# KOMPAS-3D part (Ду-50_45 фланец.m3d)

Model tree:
1. Операция без истории:1
2. Операция без истории:2
3. Операция без истории:3
4. Операция без истории:4
5. Операция без истории:5
6. Операция без истории:6
7. Операция без истории:7
8. Операция без истории:8
9. Операция без истории:9
10. Операция без истории:10
11. Операция без истории:11
12. Операция без истории:13
13. Операция без истории:12
14. Операция без истории:14
15. Операция без истории:15
16. Операция без истории:16
17. Операция без истории:17
18. Операция без истории:18
19. Операция без истории:19
20. Операция без истории:20
21. Операция без истории:21
22. Операция без истории:22
23. Операция без истории:23
24. Операция без истории:24

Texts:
  Ду-50_45 фланец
